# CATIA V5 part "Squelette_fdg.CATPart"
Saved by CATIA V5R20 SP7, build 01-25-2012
Part number: Squelette_fdg
Publications: "Plan.2", "Droite.8", "Droite.9", "Droite.10"
Bounding box of the stored display mesh (mm): x 0 to 20, y -70.711 to 7.304, z 0 to 117.956
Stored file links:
  G:\bon\Nouveau dossier\Squelette_fdg.CATPart
  C:\Documents and Settings\cgirerd\Bureau\Copie de Copie de Nouveau dossier\765.CATProduct
  G:\bon\Nouveau dossier\mecanism.skl.CATProduct
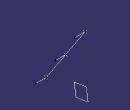
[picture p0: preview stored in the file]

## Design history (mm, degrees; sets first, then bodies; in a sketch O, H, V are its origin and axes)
Set1
  Point1 "F": linked copy from another document
  Point2 "D": linked copy from another document
  Point3 "G": linked copy from another document
  Plane1: linked copy from another document
Set2
  Line1: type PtPt, FirstPoint Point1, SecondPoint Point2
  Line2: type PtPt, FirstPoint Point2, SecondPoint Point3
  Line3: type Normal, RefPoint Point1, RefSkin Plane1, Start 0, End 20
  Line4: type Normal, RefPoint Point2, RefSkin Plane1, Start 0, End 20
  Line5: type Normal, RefPoint Point3, RefSkin Plane1, Start 0, End 20
Body1 (main body)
